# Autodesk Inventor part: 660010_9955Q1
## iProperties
Created: 2004-12
Part Number: 660010_9955Q1
Document SubType Name: Modeling
Designer: Ewald
Manufacturer: Standard
Standards Organization: Custom
Author: Ewald
Übersetzungsnorm: IGES 5.3
Dateiname: \\Ewald-2\Downloads\#CADTOOLS\Inventor 9\660010\660010_9955Q1.igs
Vorprozessor: AutoCAD-16.1s (LMS Tech) (Microsoft Windows NT Version 5.0 (x86))
Postprozessor: Build: 096e, Release: 9 RTM - Date: Thu 06/17/2004
Gesendete Einheiten: MM
Unbestimmtheit: 5.6e-07
